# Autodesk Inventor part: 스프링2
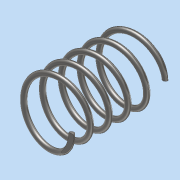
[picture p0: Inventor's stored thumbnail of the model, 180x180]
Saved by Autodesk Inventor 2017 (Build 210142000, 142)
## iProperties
Part Number: 스프링2
Material: 강철, 연강
Document SubType Name: Modeling
Designer: MRC
Density: 7.85 g/cm^3
Appearance: 반연마
Mass: 8.42324 g
Surface Area: 21.7217 cm^2
Volume: 1.07302 cm^3
Author: MRC
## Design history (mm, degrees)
sketch "스케치1"
  geometry: L1 (0, 0)-(0, 36.411); L2 (0, 36.411)-(11, 36.411); L3 (0, 0)-(11, 0); C1 r 1 at (11, 0)
  constraints: 6 end point, 2 horizontal, 1 centre point, 1 coincident, 1 vertical
  dimensions: "d0" = 36.4112 distance of L1.start L1.end (derived); "d2" = 22 diameter of L3.end L1; "d3" = 2 diameter of C1; "d4" = 22 diameter of L2.end L1
feature "코일1" pitch "d5" = 10; turns "d7" = 5; dims "d6" = 36.4112 (= d0), "d8" = 0, angle "d9" = 90 deg, angle "d10" = 90 deg, "d11" = 0, "d12" = 0
sketch "스케치2"
  geometry: L1 (-13.313, 0)-(15.035, 0); L2 (15.035, 0)-(15.035, 36.411); L3 (15.035, 36.411)-(-13.313, 36.411); L4 (-13.313, 36.411)-(-13.313, 0); 1 further point
  constraints: 8 end point, 2 parallel, 1 horizontal, 1 perpendicular
  dimensions: "d13" = 36.4112 distance of L1.end L2.end (= d0)
extrude "돌출1" sketch "스케치2" stored distance "d14" = 0; taper "d15" = 0 deg
node "솔리드1"
